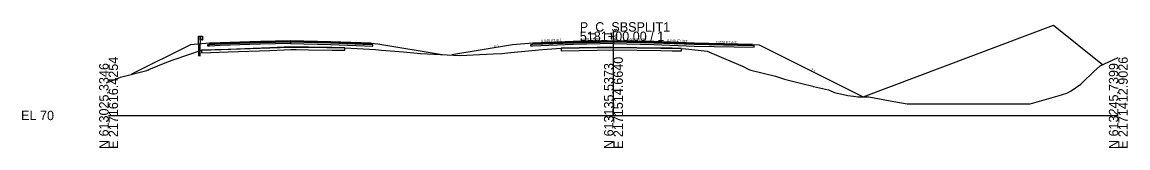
# Model space of a CAD drawing. Extents: x -26 to 1303, y -3010 to 12033.
# Drawn here: x -25.7 to 302.8, y 4990.3 to 5027.8 of the extents above; entities that cross this region are included whole.
import ezdxf

# ---------------------------------------------------------------- set-up
doc = ezdxf.new("R2010")
doc.units = 0
for name, color, linetype in [('RD_GPK_XS_Cell', 7, 'Continuous'), ('RD_PD_Final_TrvlWay', 7, 'Continuous'), ('RD_Sketch10', 7, 'Continuous'), ('RD_XS_Base', 7, 'Continuous'), ('RD_XS_ExGround', 7, 'Continuous'), ('RD_XS_ExPaveRet', 7, 'Continuous'), ('RD_XS_GR', 7, 'Continuous'), ('RD_XS_Greenside', 7, 'Continuous'), ('RD_XS_Pave', 7, 'Continuous'), ('RD_XS_PaveOvlay_CP', 7, 'Continuous'), ('RD_XS_TieSlope', 7, 'Continuous'), ('RD_XS_TX_Elev_EX', 7, 'Continuous'), ('RD_XS_TX_Elev_PR', 7, 'Continuous'), ('RD_XS_TX_Slope', 7, 'Continuous')]:
    doc.layers.add(name, color=color, linetype=linetype)

msp = doc.modelspace()

# ---------------------------------------------------------------- linework, layer by layer
at = {"layer": 'RD_GPK_XS_Cell'}
for p, q in [((150, 5000), (150, 5025)), ((0, 5000), (150, 5000)), ((150, 5000), (300, 5000))]:
    msp.add_line(p, q, dxfattribs=at)
at = {"layer": 'RD_PD_Final_TrvlWay'}
msp.add_lwpolyline([(27.17, 5017.68), (27.17, 5021.28), (26.67, 5021.24), (26.67, 5017.68)], dxfattribs=at)
at = {"layer": 'RD_Sketch10'}
msp.add_lwpolyline([(224.22, 5005.55), (280.77, 5026.95), (295.33, 5015.14)], dxfattribs=at)
at = {"layer": 'RD_XS_Base'}
for p, q in [((29.5, 5020.8), (29.5, 5021.17)), ((29.5, 5021.17), (29.63, 5021.17)), ((29.5, 5020.67), (29.5, 5020.8)), ((29.63, 5020.67), (29.5, 5020.67)), ((29.63, 5021.17), (30, 5021.19)), ((30, 5020.69), (29.63, 5020.67)), ((30, 5021.19), (33.12, 5021.31)), ((33.12, 5020.81), (30, 5020.69)), ((33.12, 5021.31), (42, 5021.67)), ((42, 5021.17), (33.12, 5020.81)), ((42, 5021.67), (45.12, 5021.73)), ((45.12, 5021.23), (42, 5021.17)), ((45.12, 5021.73), (54, 5021.91)), ((54, 5021.41), (45.12, 5021.23)), ((54, 5021.95), (54, 5022.07)), ((54, 5022.07), (54, 5021.58)), ((54, 5021.91), (54, 5022.07)), ((54, 5022.07), (54, 5021.41)), ((54, 5021.91), (54, 5021.95)), ((54, 5021.91), (54, 5021.54)), ((54, 5021.91), (54, 5021.41)), ((66, 5021.67), (54, 5021.91)), ((54, 5021.91), (54, 5021.91)), ((54, 5021.58), (54, 5021.41)), ((54, 5021.54), (54, 5021.41)), ((54, 5021.41), (54, 5021.41)), ((54, 5021.41), (54, 5021.41)), ((54, 5021.41), (66, 5021.17)), ((78, 5021.19), (66, 5021.67)), ((66, 5021.17), (78.5, 5020.67)), ((68, 5021.59), (68, 5021.59)), ((68, 5021.09), (68, 5021.09)), ((78.5, 5021.17), (78, 5021.19)), ((78, 5021.19), (78, 5021.19)), ((78.5, 5020.67), (78.5, 5021.17)), ((78.5, 5021.17), (78.5, 5021.17)), ((78.5, 5020.67), (78.5, 5020.67)), ((78.5, 5020.67), (78.5, 5020.67)), ((125.5, 5021.18), (126, 5021.2)), ((125.5, 5020.68), (125.5, 5021.18)), ((125.5, 5021.18), (125.5, 5021.18)), ((126, 5020.7), (125.5, 5020.68)), ((125.5, 5020.68), (125.5, 5020.68)), ((125.5, 5020.68), (125.5, 5020.68)), ((126, 5021.2), (138, 5021.68)), ((126, 5021.2), (126, 5021.2)), ((138, 5021.18), (126, 5020.7)), ((126, 5020.7), (126, 5020.7)), ((138, 5021.68), (150, 5021.92)), ((150, 5021.42), (138, 5021.18)), ((150, 5021.92), (150, 5022.08)), ((150, 5022.08), (150, 5021.42)), ((150, 5021.92), (150, 5021.92)), ((162, 5021.68), (150, 5021.92)), ((150, 5021.92), (150, 5021.92)), ((150, 5021.92), (150, 5021.42)), ((150, 5021.42), (150, 5021.42)), ((150, 5021.42), (162, 5021.18)), ((150, 5021.42), (150, 5021.42)), ((174, 5021.2), (162, 5021.68)), ((162, 5021.68), (162, 5021.68)), ((162, 5021.18), (162, 5021.18)), ((162, 5021.18), (174, 5020.7)), ((191.3, 5020.85), (174, 5021.2)), ((174, 5021.2), (174, 5021.2)), ((174, 5020.7), (174, 5020.7)), ((174, 5020.7), (191.8, 5020.34)), ((191.8, 5020.84), (191.3, 5020.85)), ((191.3, 5020.85), (191.3, 5020.85)), ((191.8, 5020.34), (191.8, 5020.84)), ((191.8, 5020.84), (191.8, 5020.84)), ((191.8, 5020.34), (191.8, 5020.34)), ((191.8, 5020.34), (191.8, 5020.34))]:
    msp.add_line(p, q, dxfattribs=at)
at = {"layer": 'RD_XS_ExGround'}
msp.add_lwpolyline([(0, 5009.88), (3.56, 5011.44), (11.39, 5013.44), (11.48, 5013.46), (11.57, 5013.48), (11.61, 5013.51), (11.97, 5013.65), (17.3, 5015.84), (18.9, 5016.5), (19.46, 5016.71), (27.65, 5019.42), (47.94, 5020.15), (54.12, 5020.38), (59.35, 5020.32), (70.22, 5020.19), (79.28, 5019.64), (81.06, 5019.49), (87.61, 5018.94), (92.64, 5018.46), (94.72, 5018.38), (104.46, 5017.9), (112.23, 5018.3), (114.28, 5018.41), (116.81, 5018.5), (119.47, 5018.76), (128.93, 5019.67), (134.44, 5020.01), (145.19, 5020.21), (149.93, 5020.29), (164.12, 5020.09), (167.49, 5020.04), (170.17, 5020), (171.53, 5019.87), (177.82, 5019.18), (183.43, 5016.76), (188.34, 5014.7), (190.27, 5013.72), (190.84, 5013.45), (198.16, 5011.69), (198.76, 5011.55), (200.86, 5010.85), (205.94, 5009.5), (209.28, 5008.68), (209.32, 5008.67), (209.39, 5008.65), (213.9, 5007.6), (215.69, 5006.84), (219.59, 5005.99), (221.34, 5005.72), (222.61, 5005.59), (225.91, 5005.5), (232.22, 5004.34), (237.23, 5003.47), (238.71, 5003.47), (243.13, 5003.47), (252.21, 5003.47), (264.44, 5003.47), (273.81, 5003.47), (282.08, 5005.81), (284.69, 5006.62), (286.02, 5007.34), (288.86, 5009.28), (290.38, 5010.82), (291.59, 5012), (292.59, 5012.95), (294.61, 5014.81), (300, 5017.32)], dxfattribs=at)
at = {"layer": 'RD_XS_ExPaveRet'}
for points in [[(59.35, 5020.32), (55.73, 5020.36), (54.12, 5020.38), (52.21, 5020.31), (47.94, 5020.15), (35.5, 5019.7), (27.65, 5019.42), (27.65, 5019.01), (27.65, 5018.67), (35.5, 5018.95), (47.94, 5019.4), (52.21, 5019.56), (54.12, 5019.63), (55.73, 5019.61), (59.35, 5019.57), (66.45, 5019.49), (70.22, 5019.44), (70.22, 5019.79), (70.22, 5020.19), (66.45, 5020.24), (59.35, 5020.32)], [(59.35, 5020.32), (55.73, 5020.36), (54.12, 5020.38), (52.21, 5020.31), (47.94, 5020.15), (35.5, 5019.7), (27.65, 5019.42), (27.65, 5019.01), (27.65, 5018.67), (35.5, 5018.95), (47.94, 5019.4), (52.21, 5019.56), (54.12, 5019.63), (55.73, 5019.61), (59.35, 5019.57), (66.45, 5019.49), (70.22, 5019.44), (70.22, 5019.79), (70.22, 5020.19), (66.45, 5020.24), (59.35, 5020.32)], [(170.17, 5020), (167.49, 5020.04), (164.12, 5020.09), (164.12, 5020.09), (149.93, 5020.29), (145.19, 5020.21), (145.19, 5020.21), (134.44, 5020.01), (134.44, 5020.01), (134.44, 5020.01), (134.44, 5019.26), (134.44, 5019.26), (145.19, 5019.46), (145.19, 5019.46), (149.93, 5019.54), (164.12, 5019.34), (164.12, 5019.34), (167.49, 5019.29), (170.17, 5019.25), (170.17, 5019.25), (170.17, 5019.25), (170.17, 5020), (170.17, 5020), (170.17, 5020), (170.17, 5020)], [(170.17, 5020), (167.49, 5020.04), (164.12, 5020.09), (149.93, 5020.29), (145.19, 5020.21), (134.44, 5020.01), (134.44, 5019.26), (145.19, 5019.46), (149.93, 5019.54), (164.12, 5019.34), (167.49, 5019.29), (170.17, 5019.25), (170.17, 5020)]]:
    msp.add_lwpolyline(points, dxfattribs=at)
at = {"layer": 'RD_XS_GR'}
for p, q in [((26.67, 5021.24), (26.67, 5023.68)), ((26.67, 5023.68), (26.92, 5023.68)), ((26.92, 5023.68), (27.17, 5023.68)), ((27.17, 5023.68), (27.17, 5021.28)), ((27.17, 5022.51), (27.17, 5023.68)), ((27.17, 5023.68), (27.83, 5023.68)), ((27.83, 5023.68), (27.83, 5022.51)), ((28.03, 5023.46), (27.83, 5023.68)), ((27.83, 5023.68), (27.83, 5022.81)), ((27.9, 5023.17), (28.1, 5023.38)), ((28.1, 5023.38), (28.03, 5023.46)), ((27.17, 5021.28), (26.67, 5021.24)), ((27.83, 5022.51), (27.17, 5022.51)), ((27.83, 5023.09), (27.9, 5023.17)), ((28.03, 5022.88), (27.83, 5023.09)), ((27.83, 5022.81), (27.83, 5022.51)), ((27.83, 5022.51), (27.9, 5022.58)), ((27.9, 5022.58), (28.1, 5022.8)), ((28.1, 5022.8), (28.03, 5022.88))]:
    msp.add_line(p, q, dxfattribs=at)
at = {"layer": 'RD_XS_Greenside'}
for p, q in [((24.35, 5021.06), (6.79, 5012.28)), ((80, 5021.35), (99.09, 5018.16)), ((120, 5021.04), (101.94, 5018.03)), ((193.3, 5021.01), (224.22, 5005.55))]:
    msp.add_line(p, q, dxfattribs=at)
at = {"layer": 'RD_XS_Pave'}
for p, q in [((33.12, 5021.63), (30, 5021.51)), ((30, 5021.51), (30, 5021.39)), ((33.12, 5021.47), (30, 5021.35)), ((30, 5021.35), (33.12, 5021.47)), ((30, 5021.39), (30, 5021.35)), ((30, 5021.35), (30, 5021.23)), ((30, 5021.19), (33.12, 5021.31)), ((30, 5021.23), (30, 5021.19)), ((42, 5021.99), (33.12, 5021.63)), ((42, 5021.83), (33.12, 5021.47)), ((33.12, 5021.47), (42, 5021.83)), ((33.12, 5021.31), (42, 5021.67)), ((45.12, 5022.05), (42, 5021.99)), ((45.12, 5021.89), (42, 5021.83)), ((42, 5021.83), (45.12, 5021.89)), ((42, 5021.67), (45.12, 5021.73)), ((54, 5022.23), (45.12, 5022.05)), ((54, 5022.07), (45.12, 5021.89)), ((45.12, 5021.89), (54, 5022.07)), ((45.12, 5021.73), (54, 5021.91)), ((66, 5021.99), (54, 5022.23)), ((54, 5021.95), (54, 5022.07)), ((54, 5022.07), (54, 5021.95)), ((54, 5021.91), (54, 5022.07)), ((54, 5022.07), (66, 5021.83)), ((66, 5021.83), (54, 5022.07)), ((54, 5022.07), (54, 5021.91)), ((54, 5021.91), (54, 5021.95)), ((54, 5021.95), (54, 5021.91)), ((54, 5021.91), (54, 5021.91)), ((54, 5021.91), (54, 5021.91)), ((54, 5021.91), (66, 5021.67)), ((78, 5021.51), (66, 5021.99)), ((66, 5021.83), (78, 5021.35)), ((78, 5021.35), (66, 5021.83)), ((66, 5021.67), (78, 5021.19)), ((68, 5021.91), (68, 5021.91)), ((68, 5021.75), (68, 5021.75)), ((68, 5021.75), (68, 5021.75)), ((68, 5021.59), (68, 5021.59)), ((78, 5021.35), (78, 5021.51)), ((78, 5021.51), (78, 5021.51)), ((78, 5021.35), (78, 5021.35)), ((78, 5021.35), (78, 5021.35)), ((78, 5021.19), (78, 5021.35)), ((78, 5021.35), (78, 5021.35)), ((78, 5021.19), (78, 5021.19)), ((78, 5021.19), (78, 5021.19)), ((138, 5022), (126, 5021.52)), ((138, 5021.84), (126, 5021.36)), ((126, 5021.36), (138, 5021.84)), ((126, 5021.2), (138, 5021.68)), ((126, 5021.52), (126, 5021.52)), ((126, 5021.52), (126, 5021.36)), ((126, 5021.36), (126, 5021.36)), ((126, 5021.36), (126, 5021.2)), ((126, 5021.36), (126, 5021.36)), ((126, 5021.36), (126, 5021.36)), ((126, 5021.2), (126, 5021.2)), ((126, 5021.2), (126, 5021.2)), ((150, 5022.24), (138, 5022)), ((150, 5022.08), (138, 5021.84)), ((138, 5021.84), (150, 5022.08)), ((138, 5021.68), (150, 5021.92)), ((162, 5022), (150, 5022.24)), ((150, 5021.92), (150, 5022.08)), ((150, 5022.08), (162, 5021.84)), ((162, 5021.84), (150, 5022.08)), ((150, 5022.08), (150, 5022.08)), ((150, 5022.08), (150, 5021.92)), ((150, 5021.92), (150, 5021.92)), ((150, 5021.92), (150, 5021.92)), ((150, 5021.92), (150, 5021.92)), ((150, 5021.92), (162, 5021.68)), ((174, 5021.52), (162, 5022)), ((162, 5022), (162, 5022)), ((162, 5021.84), (162, 5021.84)), ((162, 5021.84), (174, 5021.36)), ((174, 5021.36), (162, 5021.84)), ((162, 5021.84), (162, 5021.84)), ((162, 5021.68), (162, 5021.68)), ((162, 5021.68), (174, 5021.2)), ((191.3, 5021.17), (174, 5021.52)), ((174, 5021.52), (174, 5021.52)), ((174, 5021.36), (174, 5021.36)), ((174, 5021.36), (191.3, 5021.01)), ((191.3, 5021.01), (174, 5021.36)), ((174, 5021.36), (174, 5021.36)), ((174, 5021.2), (174, 5021.2)), ((174, 5021.2), (191.3, 5020.85)), ((191.3, 5021.01), (191.3, 5021.17)), ((191.3, 5021.17), (191.3, 5021.17)), ((191.3, 5021.01), (191.3, 5021.01)), ((191.3, 5021.01), (191.3, 5021.01)), ((191.3, 5020.85), (191.3, 5021.01)), ((191.3, 5021.01), (191.3, 5021.01)), ((191.3, 5020.85), (191.3, 5020.85)), ((191.3, 5020.85), (191.3, 5020.85))]:
    msp.add_line(p, q, dxfattribs=at)
at = {"layer": 'RD_XS_PaveOvlay_CP'}
for p, q in [((30, 5021.51), (42, 5021.99)), ((42, 5021.99), (54, 5022.23)), ((54, 5022.23), (66, 5021.99)), ((66, 5021.99), (78, 5021.51)), ((138, 5022), (126, 5021.52)), ((126, 5021.52), (126, 5021.52)), ((150, 5022.24), (138, 5022)), ((162, 5022), (150, 5022.24)), ((174, 5021.52), (162, 5022)), ((162, 5022), (162, 5022)), ((191.3, 5021.17), (174, 5021.52)), ((174, 5021.52), (174, 5021.52)), ((191.3, 5021.17), (191.3, 5021.17))]:
    msp.add_line(p, q, dxfattribs=at)
at = {"layer": 'RD_XS_TieSlope'}
for p, q in [((30, 5021.51), (24.35, 5021.06)), ((78, 5021.51), (80, 5021.35)), ((126, 5021.52), (120, 5021.04)), ((191.3, 5021.17), (193.3, 5021.01))]:
    msp.add_line(p, q, dxfattribs=at)

# ---------------------------------------------------------------- texts
at = {"layer": 'RD_GPK_XS_Cell'}
for s, p in [('P_C_SBSPLIT1', (140, 5025)), ('5181+00.00 / 1', (140, 5022.2)), ('EL 70', (-26, 4998.6))]:
    msp.add_text(s, height=2.8, dxfattribs=at).set_placement(p)
for s, p in [('E 2171616.4254', (2.8, 4990)), ('E 2171514.6640', (152.8, 4990)), ('E 2171412.9026', (302.8, 4990)), ('N 613025.3346', (0, 4990)), ('N 613135.5373', (150, 4990)), ('N 613245.7399', (300, 4990))]:
    msp.add_text(s, height=2.8, rotation=90, dxfattribs=at).set_placement(p)
at = {"layer": 'RD_XS_TX_Elev_EX'}
msp.add_text('90.29', height=0.6, rotation=90, dxfattribs=at).set_placement((149.7, 5022.77))
at = {"layer": 'RD_XS_TX_Elev_PR'}
msp.add_text('92.24', height=1, rotation=90, dxfattribs=at).set_placement((151.15, 5022.45))
at = {"layer": 'RD_XS_TX_Slope'}
for s, rotation, p in [('6:1', 9.4623, (114.62, 5020.2)), ('0.040 FT./FT.', 2.2906, (128.55, 5021.86)), ('0.020 FT./FT.', 1.1458, (140.19, 5022.25)), ('0.020 FT./FT.', 358.8542, (153.94, 5022.26)), ('0.040 FT./FT.', 357.7094, (165.94, 5021.94)), ('0.020 FT./FT.', 358.8542, (180.59, 5021.48)), ('2:1', 333.4349, (208.58, 5013.43))]:
    msp.add_text(s, height=0.75, rotation=rotation, dxfattribs=at).set_placement(p)

doc.saveas('drawing.dxf')
